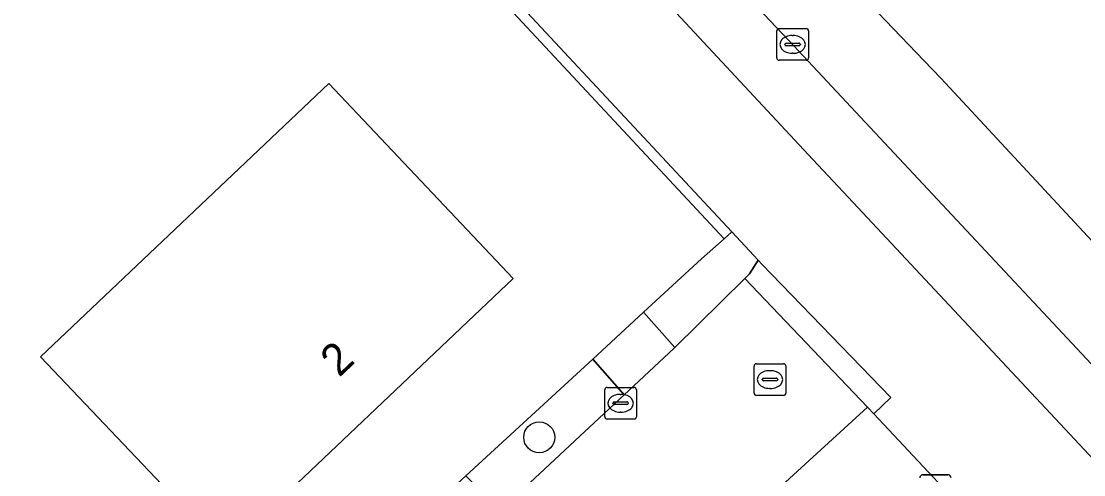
# Model space of a CAD drawing. Extents: x 162661 to 163484, y 380247 to 381230.
# Drawn here: x 163277.59 to 163311.07, y 381039.96 to 381054.25 of the extents above; entities that cross this region are included whole.
import ezdxf

# ---------------------------------------------------------------- set-up
doc = ezdxf.new("R2010")
doc.units = 0
for name, color, linetype in [('IMGEO_Berm_open', 7, 'Continuous'), ('IMGEO_Boom', 7, 'Continuous'), ('IMGEO_Erf', 7, 'Continuous'), ('IMGEO_Fietspad_gesloten', 7, 'Continuous'), ('IMGEO_Groenvoorziening', 7, 'Continuous'), ('IMGEO_Hek', 7, 'Continuous'), ('IMGEO_Kolk', 7, 'Continuous'), ('IMGEO_Pand', 7, 'Continuous'), ('IMGEO_Pand_nummerreeks', 7, 'Continuous'), ('IMGEO_Rijbaan_lokaal_gesloten', 7, 'Continuous'), ('IMGEO_Rijbaan_lokaal_onverhard', 7, 'Continuous'), ('IMGEO_Rioolput', 7, 'Continuous'), ('IMGEO_Straatnaambord', 7, 'Continuous'), ('IMGEO_Voetpad_open', 7, 'Continuous')]:
    doc.layers.add(name, color=color, linetype=linetype)

msp = doc.modelspace()

# ---------------------------------------------------------------- linework, layer by layer
at = {"layer": 'IMGEO_Berm_open'}
for points in [[(163314.848, 381043.594), (163314.647, 381043.809), (163311.194, 381047.476), (163306.575, 381052.453), (163306.036, 381053.017), (163304.107, 381055.037), (163299.085, 381060.412)], [(163297.492, 381058.211), (163297.629, 381058.041), (163301.939, 381053.48), (163304.039, 381051.234), (163315.711, 381038.75), (163343.734, 381008.697), (163351.893, 381000), (163369.825, 380980.883), (163383.497, 380966.224), (163404.827, 380943.419), (163407.337, 380940.661), (163420.715, 380926.423), (163421.985, 380925.068)]]:
    msp.add_lwpolyline(points, dxfattribs=at)
at = {"layer": 'IMGEO_Boom'}
msp.add_circle((163293.914, 381041.137), 0.489, dxfattribs=at)
at = {"layer": 'IMGEO_Erf'}
msp.add_lwpolyline([(163266.746, 381016.75), (163281.455, 381030.578), (163282.912, 381031.92), (163286.352, 381035.088), (163290.248, 381038.675), (163291.6, 381039.92), (163295.598, 381043.601), (163297.201, 381045.077), (163299.028, 381046.76), (163299.743, 381047.398), (163270.964, 381078.278), (163268.488, 381078.583), (163264.731, 381078.079), (163262.86, 381076.15), (163260.102, 381073.52), (163257.039, 381070.598), (163256.339, 381069.931), (163250.303, 381064.174), (163242.599, 381057.45)], dxfattribs=at)
msp.add_lwpolyline([(163278.201, 381043.669), (163287.281, 381052.288), (163293.096, 381046.144), (163284.027, 381037.541)], close=True, dxfattribs=at)
at = {"layer": 'IMGEO_Fietspad_gesloten'}
for points in [[(163217.057, 381141.357), (163222.96, 381135.118), (163269.7, 381085.146), (163302.54, 381049.896), (163303.348, 381049.029), (163349.187, 381000), (163381.324, 380965.637), (163403.356, 380942.043), (163438.582, 380904.399), (163442.528, 380900.205)], [(163443.416, 380902.118), (163440.156, 380905.623), (163433.683, 380912.569), (163424.587, 380922.291), (163421.985, 380925.068), (163420.715, 380926.423), (163407.337, 380940.661), (163404.827, 380943.419), (163383.497, 380966.224), (163369.825, 380980.883), (163351.893, 381000), (163343.734, 381008.697), (163315.711, 381038.75), (163304.039, 381051.234), (163301.939, 381053.48), (163297.629, 381058.041), (163294.759, 381061.126), (163256.681, 381101.881), (163256.525, 381102.09), (163254.065, 381104.768), (163246.857, 381112.468), (163234.1, 381126.005)]]:
    msp.add_lwpolyline(points, dxfattribs=at)
at = {"layer": 'IMGEO_Groenvoorziening'}
for points in [[(163268.456, 381081.408), (163267.161, 381082.796), (163266.149, 381081.824), (163264.53, 381080.265), (163265.668, 381079.045), (163264.731, 381078.079), (163268.488, 381078.583), (163270.964, 381078.278), (163299.743, 381047.398), (163299.982, 381047.611), (163272.114, 381077.486)], [(163300.544, 381046.294), (163300.815, 381046.718), (163299.982, 381047.611), (163299.743, 381047.398), (163299.028, 381046.76), (163297.201, 381045.077), (163298.188, 381043.972), (163300.394, 381046.146)], [(163296.587, 381042.478), (163295.598, 381043.601), (163291.6, 381039.92), (163292.678, 381038.833)]]:
    msp.add_lwpolyline(points, close=True, dxfattribs=at)
msp.add_lwpolyline([(163365.684, 380976.459), (163361.846, 380980.56), (163361.771, 380980.64), (163343.652, 381000), (163308.352, 381037.717), (163304.461, 381041.874), (163304.26, 381042.085), (163301.923, 381039.953), (163301.545, 381039.608), (163302.713, 381038.331), (163305.718, 381038.493), (163307.098, 381038.086), (163366.037, 380975.19)], dxfattribs=at)
at = {"layer": 'IMGEO_Hek'}
msp.add_lwpolyline([(163262.86, 381076.15), (163264.731, 381078.079), (163268.488, 381078.583), (163270.964, 381078.278), (163299.743, 381047.398)], dxfattribs=at)
at = {"layer": 'IMGEO_Kolk'}
for p, q in [((163301.474, 381054.022), (163302.326, 381054.022)), ((163301.399, 381053.096), (163301.399, 381053.948)), ((163301.887, 381053.802), (163301.912, 381053.802)), ((163302.4, 381053.948), (163302.4, 381053.096)), ((163301.658, 381053.516), (163301.658, 381053.528)), ((163302.096, 381053.479), (163301.698, 381053.479)), ((163301.701, 381053.565), (163302.099, 381053.565)), ((163302.142, 381053.528), (163302.142, 381053.516)), ((163302.326, 381053.022), (163301.474, 381053.022)), ((163301.91, 381053.242), (163301.885, 381053.242)), ((163295.978, 381041.785), (163295.978, 381042.637)), ((163296.053, 381042.711), (163296.905, 381042.711)), ((163296.979, 381042.637), (163296.979, 381041.785)), ((163296.466, 381042.491), (163296.491, 381042.491)), ((163296.237, 381042.205), (163296.237, 381042.217)), ((163296.675, 381042.168), (163296.277, 381042.168)), ((163296.28, 381042.254), (163296.678, 381042.254)), ((163296.721, 381042.217), (163296.721, 381042.205)), ((163296.905, 381041.711), (163296.053, 381041.711)), ((163296.489, 381041.931), (163296.464, 381041.931))]:
    msp.add_line(p, q, dxfattribs=at)
for points in [[(163301.474, 381054.022), (163302.326, 381054.022)], [(163301.399, 381053.096), (163301.399, 381053.948)], [(163302.4, 381053.948), (163302.4, 381053.096)], [(163302.326, 381053.022), (163301.474, 381053.022)], [(163295.978, 381041.785), (163295.978, 381042.637)], [(163296.053, 381042.711), (163296.905, 381042.711)], [(163296.979, 381042.637), (163296.979, 381041.785)], [(163296.905, 381041.711), (163296.053, 381041.711)]]:
    msp.add_lwpolyline(points, dxfattribs=at)
for centre, radius, start, end in [((163301.476, 381053.946), 0.0765, 91.552, 178.448), ((163301.476, 381053.946), 0.0765, 91.552, 178.448), ((163302.324, 381053.946), 0.0765, 1.552, 88.448), ((163302.324, 381053.946), 0.0765, 1.552, 88.448), ((163301.698, 381053.525), 0.0403, 85.8775, 175.7526), ((163301.695, 381053.515), 0.0366, 178.938, 274.7102), ((163302.099, 381053.522), 0.043, 264.8664, 352.4533), ((163302.103, 381053.527), 0.0386, 1.7309, 96.639), ((163301.476, 381053.098), 0.0765, 181.552, 268.448), ((163301.476, 381053.098), 0.0765, 181.552, 268.448), ((163302.324, 381053.098), 0.0765, 271.552, 358.448), ((163302.324, 381053.098), 0.0765, 271.552, 358.448), ((163296.055, 381042.635), 0.0765, 91.552, 178.448), ((163296.055, 381042.635), 0.0765, 91.552, 178.448), ((163296.903, 381042.635), 0.0765, 1.552, 88.448), ((163296.903, 381042.635), 0.0765, 1.552, 88.448), ((163296.277, 381042.214), 0.0403, 85.8775, 175.7526), ((163296.274, 381042.204), 0.0366, 178.938, 274.7102), ((163296.678, 381042.211), 0.043, 264.8664, 352.4533), ((163296.682, 381042.216), 0.0386, 1.7309, 96.639), ((163296.055, 381041.787), 0.0765, 181.552, 268.448), ((163296.055, 381041.787), 0.0765, 181.552, 268.448), ((163296.903, 381041.787), 0.0765, 271.552, 358.448), ((163296.903, 381041.787), 0.0765, 271.552, 358.448)]:
    msp.add_arc(centre, radius, start, end, dxfattribs=at)
for centre, major_axis, ratio, start_param, end_param in [((163301.886, 381053.522), (-0.387, 0.002), 0.722429, 4.712389, 7.853982), ((163301.911, 381053.522), (-0.39, 0.002), 0.717154, 1.570796, 4.712389), ((163296.465, 381042.211), (-0.387, 0.002), 0.722429, 4.712389, 7.853982), ((163296.49, 381042.211), (-0.39, 0.002), 0.717154, 1.570796, 4.712389)]:
    msp.add_ellipse(centre, major_axis=major_axis, ratio=ratio, start_param=start_param, end_param=end_param, dxfattribs=at)
at = {"layer": 'IMGEO_Pand'}
msp.add_lwpolyline([(163293.096, 381046.144), (163287.281, 381052.288), (163278.201, 381043.669), (163284.027, 381037.541)], close=True, dxfattribs=at)
at = {"layer": 'IMGEO_Rijbaan_lokaal_gesloten'}
for points in [[(163352.566, 381010.865), (163224.239, 381147.157), (163223.334, 381146.17), (163221.2, 381143.841), (163226.152, 381138.647), (163256.222, 381106.354), (163256.329, 381106.24), (163258.298, 381104.124), (163258.379, 381104.037), (163265.582, 381096.39), (163268.463, 381093.263), (163273.864, 381087.521), (163276.738, 381084.399), (163290.57, 381069.571), (163297.114, 381062.584), (163299.085, 381060.412), (163304.107, 381055.037), (163306.036, 381053.017), (163306.575, 381052.453), (163311.194, 381047.476), (163314.647, 381043.809), (163314.848, 381043.594), (163355.603, 381000)], [(163283.728, 381023.037), (163299.113, 381037.367), (163301.545, 381039.608), (163301.923, 381039.953), (163304.26, 381042.085), (163300.394, 381046.146), (163298.188, 381043.972), (163298.154, 381043.939), (163296.587, 381042.478), (163292.678, 381038.833), (163291.303, 381037.551), (163287.414, 381033.924), (163283.96, 381030.703), (163274.447, 381021.832), (163256.625, 381004.958), (163251.131, 380999.999)]]:
    msp.add_lwpolyline(points, dxfattribs=at)
at = {"layer": 'IMGEO_Rijbaan_lokaal_onverhard'}
msp.add_lwpolyline([(163298.154, 381043.939), (163298.188, 381043.972), (163297.201, 381045.077), (163295.598, 381043.601), (163296.587, 381042.478)], close=True, dxfattribs=at)
at = {"layer": 'IMGEO_Rioolput'}
for p, q in [((163300.685, 381042.532), (163300.685, 381043.384)), ((163300.76, 381043.458), (163301.612, 381043.458)), ((163301.686, 381043.384), (163301.686, 381042.532)), ((163300.987, 381043.001), (163301.385, 381043.001)), ((163301.173, 381043.238), (163301.198, 381043.238)), ((163300.944, 381042.952), (163300.944, 381042.964)), ((163301.382, 381042.915), (163300.984, 381042.915)), ((163301.196, 381042.678), (163301.171, 381042.678)), ((163301.428, 381042.964), (163301.428, 381042.952)), ((163301.612, 381042.458), (163300.76, 381042.458))]:
    msp.add_line(p, q, dxfattribs=at)
for points in [[(163300.685, 381042.532), (163300.685, 381043.384)], [(163300.76, 381043.458), (163301.612, 381043.458)], [(163301.686, 381043.384), (163301.686, 381042.532)], [(163301.612, 381042.458), (163300.76, 381042.458)]]:
    msp.add_lwpolyline(points, dxfattribs=at)
for centre, radius, start, end in [((163300.762, 381043.382), 0.0765, 91.552, 178.448), ((163300.762, 381043.382), 0.0765, 91.552, 178.448), ((163301.61, 381043.382), 0.0765, 1.552, 88.448), ((163301.61, 381043.382), 0.0765, 1.552, 88.448), ((163300.984, 381042.961), 0.0403, 85.8775, 175.7526), ((163301.389, 381042.963), 0.0386, 1.7309, 96.639), ((163300.981, 381042.951), 0.0366, 178.938, 274.7102), ((163301.385, 381042.958), 0.043, 264.8664, 352.4533), ((163300.762, 381042.534), 0.0765, 181.552, 268.448), ((163300.762, 381042.534), 0.0765, 181.552, 268.448), ((163301.61, 381042.534), 0.0765, 271.552, 358.448), ((163301.61, 381042.534), 0.0765, 271.552, 358.448)]:
    msp.add_arc(centre, radius, start, end, dxfattribs=at)
for centre, major_axis, ratio, start_param, end_param in [((163301.172, 381042.958), (-0.387, 0.002), 0.722429, 4.712389, 7.853982), ((163301.197, 381042.958), (-0.39, 0.002), 0.717154, 1.570796, 4.712389)]:
    msp.add_ellipse(centre, major_axis=major_axis, ratio=ratio, start_param=start_param, end_param=end_param, dxfattribs=at)
at = {"layer": 'IMGEO_Straatnaambord'}
for p, q in [((163306.005, 381039.957), (163306.795, 381039.957)), ((163306.795, 381039.957), (163306.005, 381039.957))]:
    msp.add_line(p, q, dxfattribs=at)
for centre, start, end in [((163306.005, 381039.857), 90, 180), ((163306.005, 381039.857), 90, 180), ((163306.795, 381039.857), 0, 90), ((163306.795, 381039.857), 360, 90)]:
    msp.add_arc(centre, 0.1, start, end, dxfattribs=at)
at = {"layer": 'IMGEO_Voetpad_open'}
for points in [[(163207.843, 381146.366), (163213.453, 381140.413), (163218.379, 381135.186), (163219.598, 381133.891), (163219.896, 381133.576), (163236.849, 381115.278), (163238.586, 381113.553), (163261.244, 381089.421), (163263.705, 381086.683), (163267.161, 381082.796), (163268.456, 381081.408), (163272.114, 381077.486), (163299.982, 381047.611), (163300.815, 381046.718), (163300.931, 381046.593), (163304.989, 381042.39), (163304.461, 381041.874), (163308.352, 381037.717), (163343.652, 381000)], [(163403.356, 380942.043), (163381.324, 380965.637), (163349.187, 381000), (163303.348, 381049.029), (163302.54, 381049.896), (163269.7, 381085.146), (163222.96, 381135.118), (163217.057, 381141.357)]]:
    msp.add_lwpolyline(points, dxfattribs=at)
msp.add_lwpolyline([(163300.394, 381046.146), (163304.26, 381042.085), (163304.461, 381041.874), (163304.989, 381042.39), (163300.931, 381046.593), (163300.815, 381046.718), (163300.544, 381046.294)], close=True, dxfattribs=at)

# ---------------------------------------------------------------- texts
at = {"layer": 'IMGEO_Pand_nummerreeks'}
msp.add_text('2', height=1, rotation=43.4875, dxfattribs=at).set_placement((163287.607, 381043.005))

doc.saveas('drawing.dxf')
